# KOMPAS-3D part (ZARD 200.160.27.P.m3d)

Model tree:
1. Поверхность без истории:1
2. Поверхность без истории:2
3. Поверхность без истории:3
4. Поверхность без истории:4
5. Поверхность без истории:5
6. Поверхность без истории:6
7. Поверхность без истории:7
8. Поверхность без истории:8
9. Поверхность без истории:9
10. Поверхность без истории:10
11. Поверхность без истории:11
12. Поверхность без истории:12
13. Поверхность без истории:13
14. Поверхность без истории:14
15. Поверхность без истории:15
16. Поверхность без истории:16
17. Поверхность без истории:17
18. Поверхность без истории:18
19. Поверхность без истории:19
20. Поверхность без истории:20
21. Поверхность без истории:21
22. Поверхность без истории:22
23. Поверхность без истории:23
24. Поверхность без истории:24
25. Поверхность без истории:25
26. Поверхность без истории:26
27. Поверхность без истории:27
28. Поверхность без истории:28
29. Поверхность без истории:29
30. Поверхность без истории:30
31. Поверхность без истории:31
32. Поверхность без истории:32
33. Поверхность без истории:33
34. Поверхность без истории:34
35. Поверхность без истории:35
36. Поверхность без истории:36
37. Поверхность без истории:37
38. Поверхность без истории:38
39. Поверхность без истории:39
40. Поверхность без истории:40
41. Поверхность без истории:41
42. Поверхность без истории:42
43. Поверхность без истории:43
44. Поверхность без истории:44
45. Поверхность без истории:45
46. Поверхность без истории:46
47. Поверхность без истории:47
48. Поверхность без истории:48
49. Поверхность без истории:49
50. Поверхность без истории:50
51. Поверхность без истории:51
52. Поверхность без истории:52
53. Поверхность без истории:53
54. Поверхность без истории:54
55. Поверхность без истории:55
56. Поверхность без истории:56
57. Поверхность без истории:57
58. Поверхность без истории:58
59. Поверхность без истории:59
60. Поверхность без истории:60
61. Поверхность без истории:61
62. Поверхность без истории:62
63. Поверхность без истории:63
64. Поверхность без истории:64
65. Поверхность без истории:65
66. Поверхность без истории:66
67. Поверхность без истории:67
68. Поверхность без истории:68
69. Поверхность без истории:69
70. Поверхность без истории:70
71. Поверхность без истории:71
72. Поверхность без истории:72
73. Поверхность без истории:73
74. Поверхность без истории:74
75. Поверхность без истории:75
76. Поверхность без истории:76
77. Поверхность без истории:77
78. Поверхность без истории:78
79. Поверхность без истории:79
80. Поверхность без истории:80
81. Поверхность без истории:81
82. Поверхность без истории:82
83. Поверхность без истории:83
84. Поверхность без истории:84
85. Поверхность без истории:85
86. Поверхность без истории:86
87. Поверхность без истории:87
88. Поверхность без истории:88
89. Поверхность без истории:89
90. Поверхность без истории:90
91. Поверхность без истории:91
92. Поверхность без истории:92
93. Поверхность без истории:93
94. Поверхность без истории:94
95. Поверхность без истории:95
96. Поверхность без истории:96
97. Поверхность без истории:97
98. Поверхность без истории:98
99. Поверхность без истории:99
100. Поверхность без истории:100
101. Поверхность без истории:101
102. Поверхность без истории:102
103. Поверхность без истории:103
104. Поверхность без истории:104
105. Поверхность без истории:105
106. Поверхность без истории:106
107. Поверхность без истории:107
108. Поверхность без истории:108
109. Поверхность без истории:109
110. Поверхность без истории:110
111. Поверхность без истории:111
112. Поверхность без истории:112
113. Поверхность без истории:113
114. Поверхность без истории:114
115. Поверхность без истории:115
116. Поверхность без истории:116
117. Поверхность без истории:117
118. Поверхность без истории:118
119. Поверхность без истории:119
120. Поверхность без истории:120
121. Поверхность без истории:121
122. Поверхность без истории:122
123. Поверхность без истории:123
124. Поверхность без истории:124
125. Поверхность без истории:125
126. Поверхность без истории:126
127. Поверхность без истории:127
128. Поверхность без истории:128
129. Поверхность без истории:129
130. Поверхность без истории:130
131. Поверхность без истории:131
132. Поверхность без истории:132

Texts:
  ЗАРД 200.160.27-ХХ.Р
